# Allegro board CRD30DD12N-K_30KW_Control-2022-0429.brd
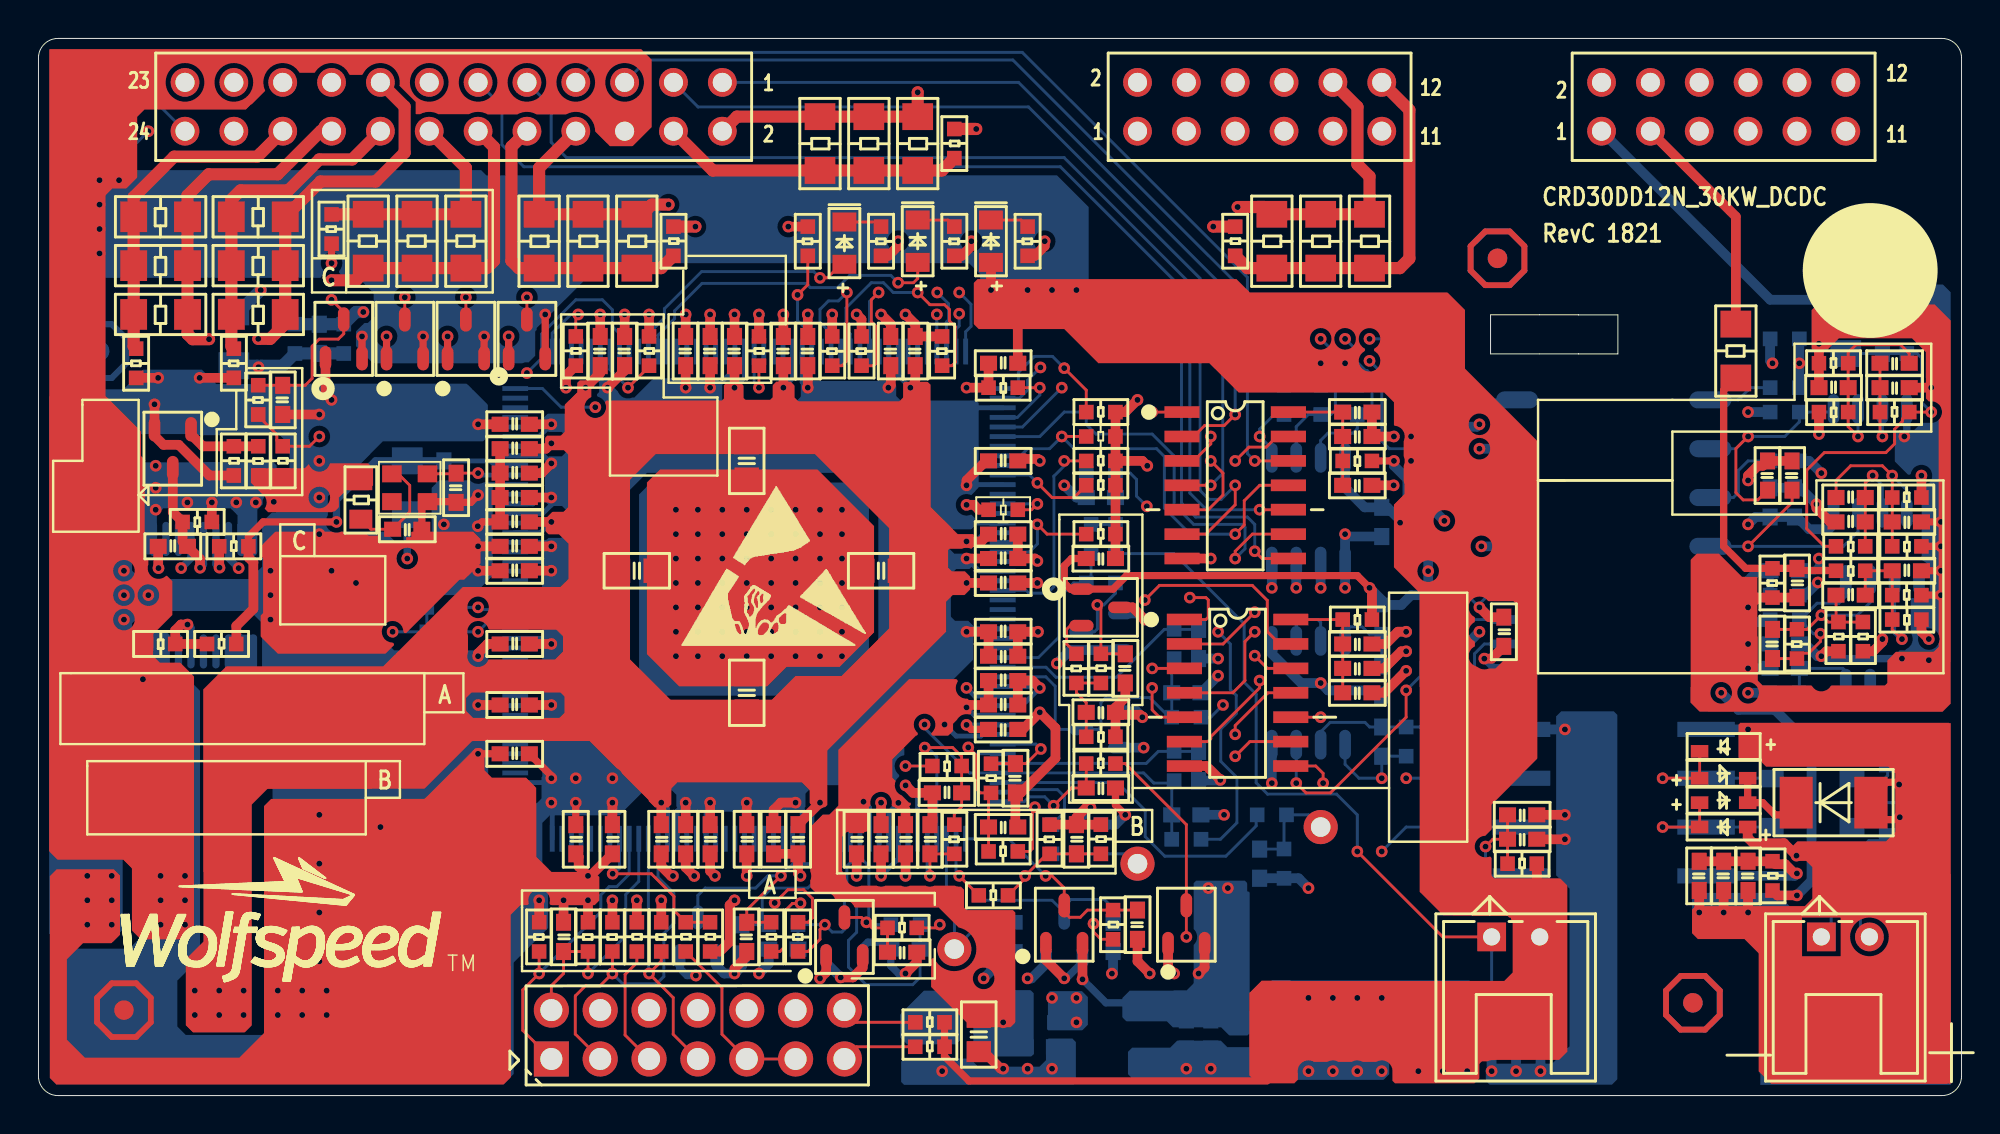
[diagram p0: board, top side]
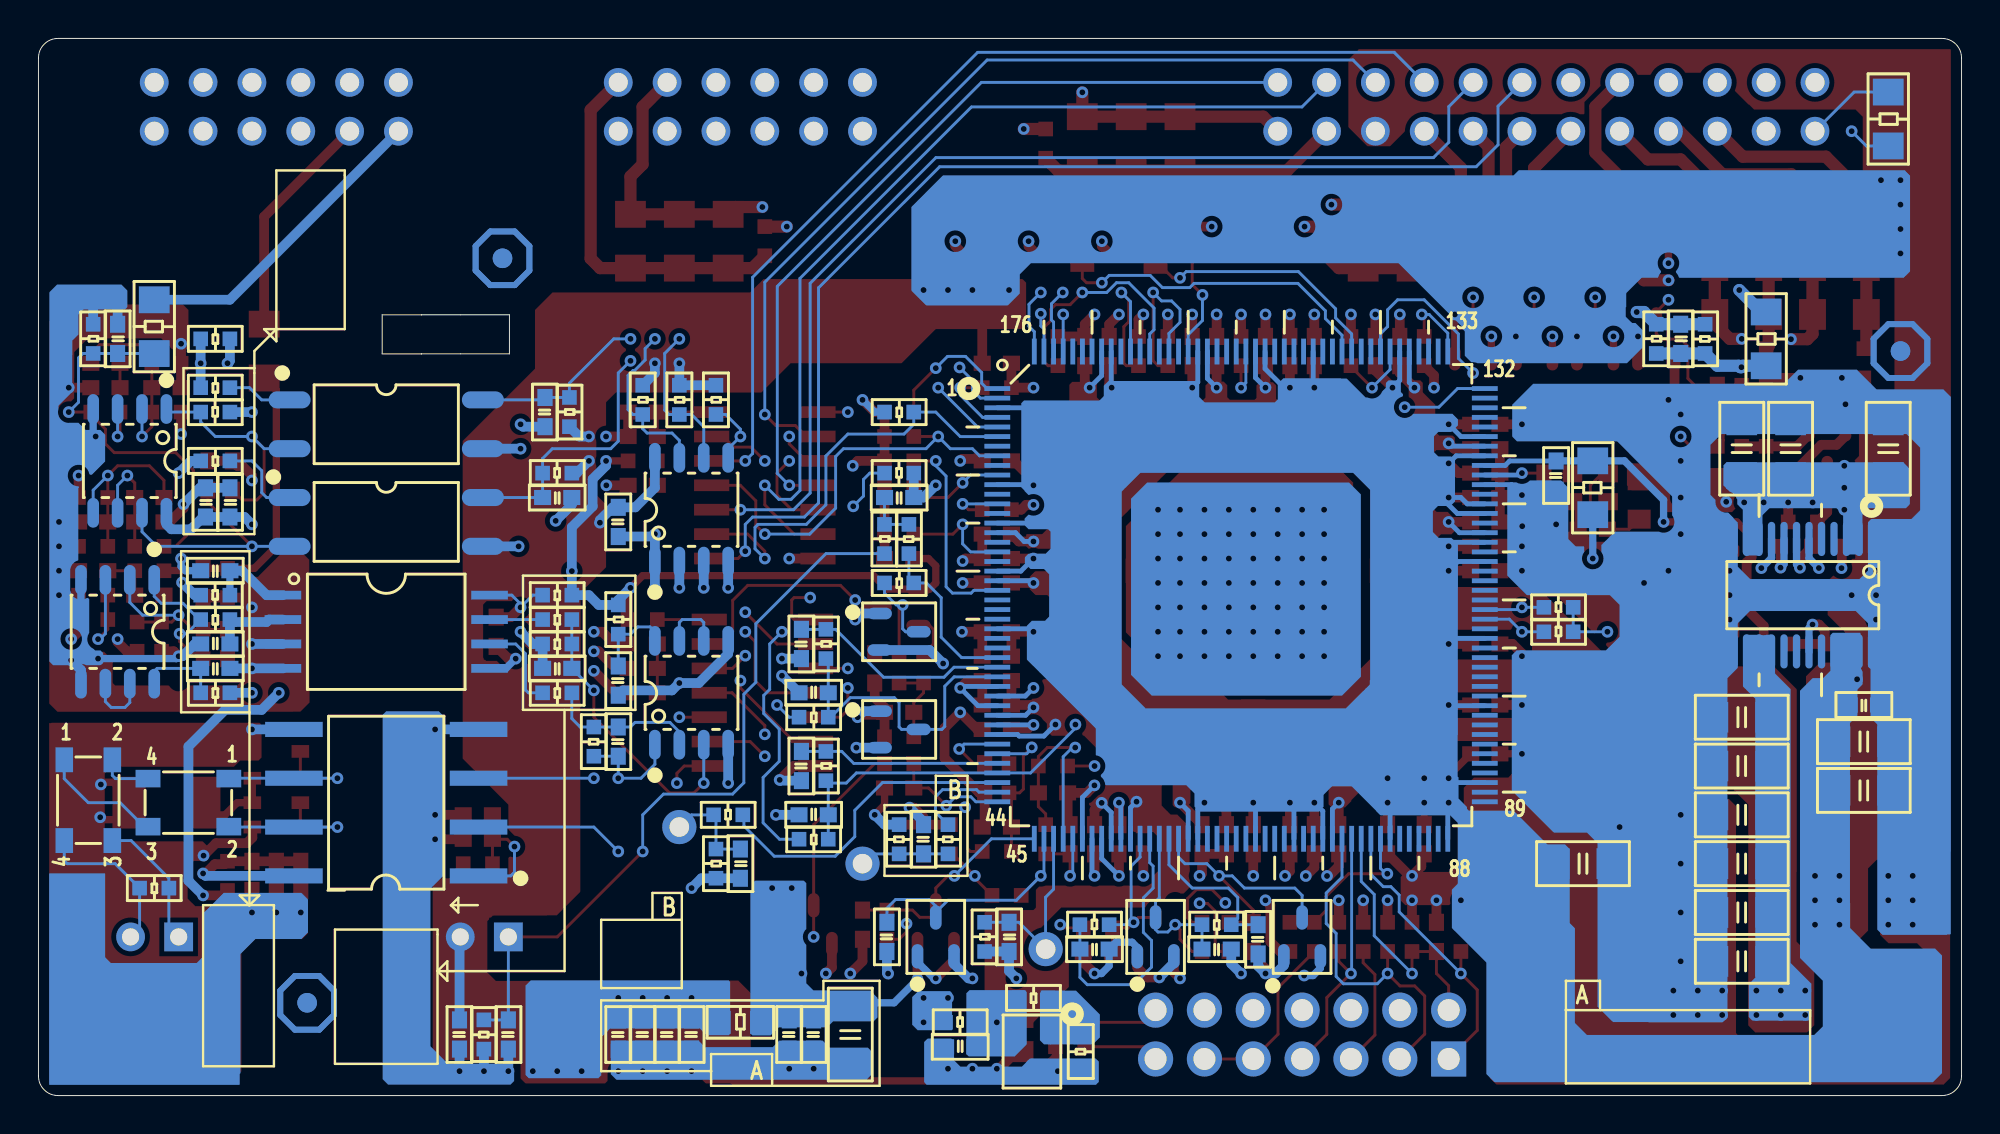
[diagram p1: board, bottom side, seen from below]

Outline 100 x 55 mm; copper layers: TOP, ART02, ART03, BOTTOM. Coordinates in mm from the lower left corner of the outline.
Outline path: 0,53.98 0,1.02 arc(0.3,0.3) 1.02,0 98.98,0 arc(99.7,0.3) 100,1.02 100,53.98 arc(99.7,54.7) 98.98,55 1.02,55 arc(0.3,54.7) 0,53.98 ; 75.51,40.62 80.08,40.62 80.08,40.62 82.13,40.62 82.13,38.59 80.08,38.59 80.08,38.59 75.51,38.59 75.51,40.62

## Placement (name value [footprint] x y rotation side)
C237  22n  [C0603]  91.44 26.67 90 top
C378  0.1u  [C0603]  27.3 8.26 90 top
C396  0.1u  [C0603]  69.85 29.84 270 bottom
C397  680p  [C0603]  52.07 2.54 0 bottom
C398  0.1u  [C0603]  69.85 3.17 270 bottom
C399  0.1u  [C0603]  68.58 3.17 270 bottom
C400  0.1u  [C0603]  67.31 3.17 270 bottom
C401  0.1u  [C0603]  66.04 3.17 270 bottom
C402  0.1u  [C0603]  60.96 3.17 270 bottom
C403  0.1u  [C0603]  59.69 3.17 270 bottom
C404  4.7u  [C1206]  57.78 3.17 270 bottom
C405  1u  [C0603]  78.11 3.17 270 bottom
C407  0.47u  [C0603]  75.56 3.17 270 bottom
C408  0.47u  [C0603]  55.24 31.11 180 bottom
C445  0.1u  [C0603]  90.81 27.3 180 bottom
C446  2.2n  [C0603]  90.81 23.5 0 bottom
C447  0.1u  [C0603]  76.2 24.13 90 top
C448  0.33n  [C0603]  73.03 22.23 180 bottom
C449  0.33n  [C0603]  69.85 18.41 270 bottom
C451  0.47u  [C0603]  69.85 21.59 270 bottom
C452  4.7n  [C0603]  57.15 8.89 270 top
C453  0.15n  [C0603]  97.16 27.3 180 top
C454  0.15n  [C0603]  94.23 26.04 180 top
C455  0.15n  [C0603]  90.17 23.5 270 top
C457  0.47u  [C0603]  90.81 22.23 180 bottom
C458  0.47n  [C0603]  96.52 36.83 0 top
C459  0.1u  [C0603]  93.34 36.83 180 top
C460  0.15n  [C0603]  96.52 38.1 0 top
C462  0.47u  [C0603]  90.04 30.86 90 bottom
C463  2.2n  [C0603]  73.66 35.56 270 bottom
C464  2.2n  [C0603]  73.03 31.11 180 bottom
C465  0.47n  [C0603]  94.23 29.84 180 top
C466  0.15n  [C0603]  94.23 31.11 180 top
C467  0.12n  [C0603]  97.16 29.84 0 top
C471  1u  [C0603]  77.15 14.61 0 top
C472  0.1u  [C0603]  77.15 13.34 0 top
C473  1u  [C0603]  86.36 11.43 270 top
C474  0.1u  [C0603]  88.9 11.43 270 top
C475  0.01u  [C0603]  87.63 11.43 270 top
C488  2.2n  [C0603]  53.98 13.34 90 top
C489  4.7n  [C0603]  55.88 8.26 270 bottom
C492  0.01u  [C0603]  55.24 19.94 0 top
C493  0.01u  [C0603]  56.52 22.23 270 top
C494  0.1u  [C0603]  55.24 27.94 0 top
C496  10u  [C1206]  11.43 33.66 90 bottom
C497  10u  [C1206]  8.89 33.66 90 bottom
C499  0.1u  [C0603]  5.08 20.32 180 bottom
C500  10u  [C1206]  5.08 18.41 180 bottom
C501  10u  [C1206]  5.08 15.88 180 bottom
C504  10u  [C1206]  3.81 33.66 90 bottom
C505  0.1u  [C0603]  6.99 28.57 180 top
C506  10u  [C1206]  19.68 12.06 180 bottom
C507  10u  [C1206]  11.43 14.61 0 bottom
C508  10u  [C1206]  11.43 12.06 0 bottom
C509  10u  [C1206]  11.43 17.14 0 bottom
C510  10u  [C1206]  11.43 9.53 0 bottom
C511  10u  [C1206]  11.43 6.99 0 bottom
C512  2.2u  [C0805]  36.83 33.02 270 top
C513  2.2u  [C0805]  43.81 27.3 180 top
C514  2.2u  [C0805]  36.83 20.95 90 top
C515  2.2u  [C0805]  31.11 27.3 0 top
C516  10u  [C1206]  11.43 19.68 0 bottom
C519  22n  [C0603]  21.08 32.26 270 bottom
C520  0.1u  [C0603]  50.16 38.1 180 top
C521  2.2u  [C0603]  50.16 19.05 0 top
C522  2.2u  [C0603]  45.59 38.73 270 top
C523  2.2u  [C0603]  44.32 38.73 270 top
C524  2.2u  [C0603]  40.01 38.73 270 top
C525  2.2u  [C0603]  38.73 38.73 270 top
C526  2.2u  [C0603]  36.2 38.73 270 top
C527  2.2u  [C0603]  34.92 38.73 270 top
C528  2.2u  [C0603]  33.66 38.73 270 top
C529  2.2u  [C0603]  30.48 38.73 270 top
C530  2.2u  [C0603]  29.21 38.73 270 top
C531  2.2u  [C0603]  24.77 34.92 180 top
C532  2.2u  [C0603]  24.77 33.66 180 top
C533  2.2u  [C0603]  24.77 32.38 180 top
C534  2.2u  [C0603]  24.77 31.11 180 top
C535  2.2u  [C0603]  24.77 29.84 180 top
C536  2.2u  [C0603]  24.77 28.57 180 top
C537  2.2u  [C0603]  24.77 27.3 180 top
C538  2.2u  [C0603]  24.77 23.5 180 top
C539  2.2u  [C0603]  24.77 20.32 180 top
C540  2.2u  [C0603]  24.77 17.78 180 top
C541  2.2u  [C0603]  27.94 13.34 90 top
C542  2.2u  [C0603]  29.84 13.34 90 top
C543  2.2u  [C0603]  32.38 13.34 90 top
C544  2.2u  [C0603]  33.66 13.34 90 top
C545  2.2u  [C0603]  34.92 13.34 90 top
C546  2.2u  [C0603]  36.83 13.34 90 top
C547  2.2u  [C0603]  38.23 13.34 90 top
C548  2.2u  [C0603]  39.5 13.34 90 top
C549  2.2u  [C0603]  45.09 13.34 90 top
C550  2.2u  [C0603]  43.81 13.34 90 top
C551  2.2u  [C0603]  42.55 13.34 90 top
C552  0.1u  [C0603]  50.16 22.86 0 top
C553  0.1u  [C0603]  50.16 33.02 180 top
C554  2.2u  [C0603]  50.16 29.21 180 top
C555  0.1u  [C0603]  50.16 27.94 180 top
C556  2.2u  [C0603]  50.16 26.67 180 top
C557  0.1u  [C0603]  50.16 24.13 180 top
C558  2.2u  [C0603]  50.16 21.59 180 top
C559  2.2u  [C0603]  50.16 20.32 180 top
C560  0.1u  [C0603]  68.58 35.56 0 top
C561  0.01u  [C0603]  68.58 31.75 0 top
C562  1u  [C0603]  68.58 34.29 0 top
C563  0.1u  [C0603]  68.58 23.5 0 top
C564  0.01u  [C0603]  68.58 20.95 0 top
C565  1u  [C0603]  68.58 22.23 0 top
C566  0.47u  [C0603]  91.31 30.86 90 bottom
C592  2.2u  [C0805]  48.9 3.17 270 top
C593  120p  [C0603]  44.91 7.46 0 top
C594  0.47n  [C0603]  95.89 39.37 90 bottom
C595  100n  [C0603]  45.09 7.62 180 bottom
C596  120p  [C0603]  38.73 7.62 180 bottom
C597  100n  [C0603]  36.58 8.13 270 bottom
C598  2.2n  [C0603]  55.24 16 0 top
C687  0.01u  [C0603]  49.53 8.26 90 bottom
C690  0.01u  [C0603]  53.98 13.34 270 bottom
C691  0.01u  [C0603]  63.5 12.06 90 bottom
C697  0.12n  [C0603]  12.7 36.2 270 top
C698  2.2n  [C0603]  14.61 39.37 90 bottom
C699  1n  [C0603]  36.83 8.26 270 top
C703  100n  [C0603]  60.33 23.5 270 bottom
C704  120p  [C0603]  59.69 20.95 0 bottom
C705  100n  [C0603]  60.33 17.14 270 bottom
C706  120p  [C0603]  59.69 14.61 0 bottom
C707  100n  [C0603]  50.8 16.51 270 top
C708  120p  [C0603]  50.16 13.97 0 top
C709  100n  [C0603]  46.35 13.34 90 top
C710  120p  [C0603]  47.24 15.75 180 top
C711  2.2u  [C0603]  19.18 29.46 0 top
C712  0.022n  [C0603]  21.72 31.62 270 top
C713  22n  [C0603]  91.19 32.26 270 top
C714  22n  [C0603]  89.92 32.26 270 top
D85  BAV99  [SOT-23]  55.24 24.13 270 bottom
D86  BAV99  [SOT-23]  34.29 8.26 180 bottom
D89  BAV99  [SOT-23]  53.34 8.89 0 top
D90  BAV99  [SOT-23]  41.91 8.26 180 bottom
D92  BAV99  [SOT-23]  55.24 19.05 270 bottom
D95  BAV99  [SOT-23]  15.88 39.37 0 top
D102  RC-CL-170R-0805  [LED0805]  41.91 44.35 90 top
D103  RC-CL-170R-0805  [LED0805]  45.72 44.45 90 top
D104  RC-CL-170R-0805  [LED0805]  49.53 44.45 90 top
D110  BAS21WS-TP  [SOD-323]  87.63 13.97 180 top
D111  SMBJ15CA  [SMB]  93.34 15.24 180 top
D112  BAS21WS-TP  [SOD-323]  87.63 15.24 0 top
D113  BAS21WS-TP  [SOD-323]  87.63 17.91 180 top
D114  BAS21WS-TP  [SOD-323]  87.63 16.51 0 top
D115  BAV99  [SOT-23]  53.34 8.26 180 bottom
D124  BAV99  [SOT-23]  25.4 39.37 0 top
D125  BAV99  [SOT-23]  22.23 39.37 0 top
D126  BAV99  [SOT-23]  19.05 39.37 0 top
D127  BAV99  [SOT-23]  41.91 8.26 0 top
D128  BAV99  [SOT-23]  59.69 8.89 0 top
DAC_1  TP  [1MMTESTPOINT]  47.62 7.62 180 bottom
DAC_4  TP  [1MMTESTPOINT]  57.15 12.06 0 bottom
DAC_5  TP  [1MMTESTPOINT]  66.67 13.97 180 bottom
J2  PIN2*12-2.54-F  [CON_2MM54_12X2]  21.59 51.44 180 top
J3  PIN2*6-2.54-F  [CON_2MM54_6X2]  63.5 51.44 0 top
J4  PIN2*6-2.54-F  [CON_2MM54_6X2]  87.63 51.44 0 top
J5  2*7P 2.54  [CON_2MM54_7X2]  34.29 3.17 180 top
J11  XHB2.54-2P-F  [CON_2MM54_2X1]  92.71 8.26 180 top
J17  1*2P  [CONNECT_2MM54_2X1]  75.56 8.26 180 top
L21  33uH 0.2A  [R0805]  63.5 3.81 0 bottom
NOREF  -  []  350.41 18.16 0 top
NOREF#2  -  []  0.01 -3.22 0 top
NOREF#3  -  []  30.85 0 90 top
NOREF#4  #VAL  [unnamed#2]  75.87 43.56 0 top
NOREF#5  #VAL  [unnamed#2]  86.03 4.83 0 top
NOREF#6  -  []  38.34 26.64 0 top
NOREF#7  -  []  0.01 -5.17 0 top
NOREF#8  -  []  364.26 48.78 0 top
NOREF#9  -  []  204.89 111.18 0 top
NOREF#10  #VAL  [unnamed#2]  4.45 4.45 0 top
NOREF#11  -  []  95.25 42.93 0 top
NOREF#12  -  []  33.5 0 90 top
NOREF#13  #VAL  [unnamed#2]  75.87 43.56 180 bottom
NOREF#14  #VAL  [unnamed#2]  3.17 38.73 180 bottom
NOREF#15  #VAL  [unnamed#2]  75.87 43.56 180 bottom
NOREF#16  #VAL  [unnamed#2]  86.03 4.83 180 bottom
NOREF#17  #VAL  [unnamed#2]  86.03 4.83 180 bottom
NOREF#18  #VAL  [unnamed#2]  3.17 38.73 180 bottom
Q1  2N7002/SOT  [SOT-23]  6.99 33.66 180 top
R49  620K  [R1206]  3.81 50.81 90 bottom
R58  24K  [R0603]  52.58 13.34 270 top
R133  12K  [R0603]  90.17 26.67 270 top
R327  1R  [R0603]  31.75 38.73 90 top
R400  1R  [R0603]  37.47 38.73 90 top
R404  10k  [R0603]  26.04 8.26 270 top
R405  10k  [R0603]  29.84 8.26 270 top
R406  10k  [R0603]  32.38 8.26 270 top
R407  10k  [R0603]  34.92 8.26 90 top
R408  0  [R0603]  33.66 8.26 90 top
R409  0  [R0603]  31.11 8.26 90 top
R410  470  [R0603]  28.57 8.26 270 top
R411  2.2k  [R0603]  46.35 3.81 180 top
R412  2.2k  [R0603]  46.35 2.54 180 top
R416  2k  [R0603]  55.24 35.56 180 bottom
R417  2k  [R0603]  55.24 34.29 180 top
R418  2k  [R0603]  46.99 38.73 270 top
R419  2k  [R0603]  41.27 38.73 270 top
R420  2k  [R0603]  55.24 29.21 180 top
R421  2k  [R0603]  55.24 35.56 180 top
R422  2k  [R0603]  40.01 44.45 270 top
R423  2k  [R0603]  42.8 38.73 270 top
R424  2k  [R0603]  50.16 36.83 0 top
R425  2k  [R0603]  55.24 33.02 180 top
R437  10k  [R0603]  64.77 36.2 90 bottom
R438  10k  [R0603]  66.67 36.2 90 bottom
R439  10k  [R0603]  68.58 36.2 90 bottom
R440  200  [R0603]  52.07 3.81 0 bottom
R441  1.5k  [R0603]  48.26 5.08 180 bottom
R442  4.7k  [R0603]  45.8 2.29 270 bottom
R443  2k  [R0603]  43.81 44.45 270 top
R444  2k  [R0603]  47.62 44.45 270 top
R445  2k  [R0603]  51.44 44.45 270 top
R446  10k  [R0603]  76.83 3.17 270 bottom
R447  3.3k  [R0603]  56.01 28.96 90 bottom
R482  2k  [R0603]  90.81 24.77 180 bottom
R483  10k  [R0603]  73.03 24.77 180 bottom
R484  10k  [R0603]  73.03 23.5 180 bottom
R485  10k  [R0603]  73.03 20.95 180 bottom
R486  10k  [R0603]  71.12 18.41 270 bottom
R487  2k  [R0603]  55.88 8.89 90 top
R488  150k  [R0603]  94.23 27.3 0 top
R489  100k  [R0603]  97.16 26.04 180 top
R491  100k  [R0603]  91.44 23.5 270 top
R492  1M  [R0603]  97.16 24.77 0 top
R493  1M  [R0603]  94.87 23.88 90 top
R494  150k  [R0603]  93.6 23.88 90 top
R495  2k  [R0603]  96.52 35.56 180 top
R496  2.2k  [R0603]  93.34 35.56 0 top
R497  3.3k  [R0603]  93.34 38.1 180 top
R500  3K  [R0603]  90.81 36.83 180 bottom
R502  15k  [R0603]  72.39 35.56 90 bottom
R503  3K  [R0603]  90.81 33.02 180 bottom
R505  15k  [R0603]  73.03 32.38 0 bottom
R506  1k  [R0603]  94.23 28.57 0 top
R507  15k  [R0603]  97.16 31.11 180 top
R508  1k  [R0603]  97.16 28.57 0 top
R514  620  [R0603]  20.95 24.13 0 bottom
R515  10k  [R0603]  20.95 25.4 0 bottom
R516  0  [R0603]  90.17 11.43 90 top
R517  120  [R0603]  93.98 10.79 180 bottom
R528  24k  [R0603]  55.24 13.34 90 top
R529  1k  [R0603]  49.66 10.41 180 top
R532  100  [R0603]  53.98 22.23 270 top
R533  470k  [R0603]  55.24 18.67 0 top
R534  3.3k  [R0603]  55.24 22.23 90 top
R536  10k  [R0603]  8.26 29.84 0 top
R537  1.5k  [R0603]  11.43 33.02 270 top
R538  12k  [R0603]  10.16 33.02 90 top
R540  100k  [R0603]  6.35 23.5 0 top
R541  0R  [R0603]  9.53 23.5 180 top
R546  10k  [R1206]  19.18 31.62 270 bottom
R547  0  [R0603]  10.16 28.57 180 top
R549  2.2R  [R0603]  68.58 33.02 0 top
R550  2.2R  [R0603]  68.58 24.77 0 top
R569  10k  [R0603]  90.81 35.56 0 bottom
R573  620k  [R1206]  88.27 38.73 270 top
R574  560k  [R1206]  93.98 40.01 270 bottom
R575  12K  [R0603]  97.16 39.37 90 bottom
R580  20R  [R1206]  11.43 45.72 0 top
R581  20R  [R1206]  11.43 43.18 0 top
R582  20R  [R1206]  11.43 40.64 0 top
R583  100  [R0603]  44.91 8.73 180 top
R588  0  [R0603]  10.16 38.1 270 top
R592  10R  [R0603]  90.81 20.95 180 bottom
R593  10R  [R0603]  90.81 26.04 0 bottom
R594  10R  [R0603]  73.03 26.04 180 bottom
R595  10R  [R0603]  69.85 24.77 90 bottom
R597  10R  [R0603]  90.81 39.37 180 bottom
R598  10R  [R0603]  77.15 12.06 180 top
R599  1k  [R0603]  45.09 8.89 0 bottom
R602  100  [R0603]  39.5 8.26 270 top
R603  20R  [R1206]  6.35 45.72 0 top
R604  20R  [R1206]  6.35 43.18 0 top
R605  20R  [R1206]  6.35 40.64 0 top
R606  1k  [R0603]  38.73 8.89 180 bottom
R607  1k  [R0603]  55.24 17.27 180 top
R610  2k  [R0603]  55.24 31.75 180 top
R611  2k  [R0603]  50.16 30.48 0 top
R673  100k  [R0603]  50.8 8.26 90 bottom
R678  1k  [R0603]  52.7 13.34 270 bottom
R679  1k  [R0603]  64.14 14.61 0 bottom
R680  100k  [R0603]  55.24 13.34 270 bottom
R681  100k  [R0603]  64.77 12.06 90 bottom
R689  1k  [R0603]  11.43 36.2 270 top
R691  10k  [R0603]  12.7 33.02 90 top
R692  24k  [R0603]  15.88 39.37 90 bottom
R693  1k  [R0603]  38.1 8.26 90 top
R694  620K  [R1206]  10.16 39.37 90 bottom
R695  24K  [R0603]  13.34 39.37 270 bottom
R702  0  [R0603]  5.08 38.1 270 top
R703  2k  [R0603]  27.94 38.73 90 top
R704  2k  [R0603]  55.24 32.38 0 bottom
R705  0  [R0603]  15.24 45.09 270 top
R706  1k  [R0603]  59.05 23.5 90 bottom
R707  100  [R0603]  59.69 19.68 180 bottom
R708  20R  [R1206]  22.23 44.45 270 top
R709  20R  [R1206]  19.68 44.45 270 top
R710  20R  [R1206]  17.14 44.45 270 top
R711  0  [R0603]  47.62 49.53 90 top
R712  1k  [R0603]  59.05 17.14 90 bottom
R713  100  [R0603]  59.69 13.34 180 bottom
R714  20R  [R1206]  40.64 49.53 90 top
R715  20R  [R1206]  45.72 49.53 90 top
R716  20R  [R1206]  43.18 49.53 90 top
R717  0  [R0603]  33.02 44.45 90 top
R718  1k  [R0603]  49.53 16.51 90 top
R719  100  [R0603]  50.16 12.7 180 top
R720  20R  [R1206]  31.11 44.45 90 top
R721  20R  [R1206]  28.57 44.45 90 top
R722  20R  [R1206]  26.04 44.45 90 top
R723  0  [R0603]  62.23 44.45 90 top
R724  1k  [R0603]  47.62 13.34 270 top
R725  100  [R0603]  47.24 17.14 0 top
R726  20R  [R1206]  69.22 44.45 90 top
R727  20R  [R1206]  66.67 44.45 90 top
R728  20R  [R1206]  64.14 44.45 90 top
R729  NA  [R0603]  54.74 28.96 270 bottom
R730  0  [R0603]  55.24 26.67 180 bottom
R731  10R  [R0805]  16.76 30.99 90 top
T1  TRNSFMR TV105  [4532]  92.2 15.24 0 bottom
T2  TRNSFMR TV105  [4532]  97.41 15.37 270 bottom
U9  AZ431  [SOT23_1-32]  48.34 2.29 0 bottom
U28  TMS320F28377D  [LQFP176-050-2424]  37.47 26.04 270 bottom
U32  24C16BT-I/SN  [SOIC-8]  66.04 30.48 90 bottom
U43  ACPL-C870-500E  [SSO-8]  81.92 24.13 270 bottom
U44  OPA2376  [SOIC-8]  95.89 24.13 270 bottom
U45  OPA2376  [SOIC-8]  66.04 20.95 90 bottom
U48  LM2903  [SOIC-8]  95.25 33.02 270 bottom
U53  1050  [SO-G8]  81.92 15.24 0 bottom
U55  LM50CIM3  [SOT-23]  55.24 25.4 270 top
U57  TPS70445PWP_TSSOP24  [TSSOP24]  8.26 26.04 270 bottom
U58  MC74VHCT50A_SOIC14  [SOIC14]  62.23 31.75 0 top
U59  MC74VHCT50A_SOIC14  [SOIC14]  62.35 20.95 0 top
U60  -  [TCLT1003]  81.92 34.92 180 bottom
U61  -  [TCLT1003]  81.92 29.84 180 bottom
Y3  OSC4_250x200  [OSC4_250X200]  19.3 31.62 0 top

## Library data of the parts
C237 C378 C396-C403 C405 C407 C408 C445-C449 C451-C455 C457-C460 C462-C467 C471-C475 C488 C489 C492-C494 C499 C505 C519-C566 C593-C598 C687 C690 C691 C697-C699 C703-C710 = C0603: Tolerance: #TOL; User Part Number: HAMP
C404 C496 C497 C500 C501 C504 C506-C511 C516 = C1206: Tolerance: #TOL; User Part Number: HAMP
C512-C515 C592 = C0805: Tolerance: #TOL; User Part Number: HAMP
C711-C714 = C0603: User Part Number: HAMP; Tolerance: #TOL
D85 D86 D89 D90 D92 D95 D115 D124-D128 Q1 U55 = SOT-23: Tolerance: #TOL; User Part Number: HAMP
D102-D104 = LED0805: Tolerance: #TOL; User Part Number: HAMP
D110 D112-D114 = SOD-323: Tolerance: #TOL; User Part Number: HAMP
D111 = SMB: Tolerance: #TOL; User Part Number: HAMP
DAC_1 DAC_4 DAC_5 = 1MMTESTPOINT: User Part Number: HAMP; Tolerance: #TOL
J2 = CON_2MM54_12X2: Tolerance: #TOL; User Part Number: HAMP
J3 J4 = CON_2MM54_6X2: Tolerance: #TOL; User Part Number: HAMP
J5 = CON_2MM54_7X2: Tolerance: #TOL; User Part Number: HAMP
J11 = CON_2MM54_2X1: Tolerance: #TOL; User Part Number: HAMP
J17 = CONNECT_2MM54_2X1: Tolerance: #TOL; User Part Number: HAMP
L21 = R0805: Tolerance: #TOL; User Part Number: HAMP
NOREF#4 NOREF#5 NOREF#10 NOREF#13-NOREF#18 = -: Tolerance: #TOL; User Part Number: HAMP
R49 R546 R573 R574 R580-R582 R603-R605 R694 R708-R710 R714-R716 R720-R722 R726-R728 = R1206: Tolerance: #TOL; User Part Number: HAMP
R58 R133 R327 R400 R404-R412 R416-R425 R437-R447 R482-R489 R491-R497 R500 R502 R503 R505-R508 R514-R517 R528 R529 R532-R534 R536-R538 R540 R541 R547 R549 R550 R569 R575 R583 R588 R592-R595 R597-R599 R602 R606 R607 R610 R611 R673 R678-R681 R689 R691-R693 R695 R702-R707 R711-R713 R717-R719 R723-R725 R729 R730 = R0603: Tolerance: #TOL; User Part Number: HAMP
R731 = R0805: User Part Number: HAMP; Tolerance: #TOL
T1 T2 = 4532: Tolerance: #TOL; User Part Number: HAMP
U9 = SOT23_1-32: Tolerance: #TOL; User Part Number: HAMP
U28 = LQFP176-050-2424: Tolerance: #TOL; User Part Number: HAMP
U32 U44 U45 U48 = SOIC-8: Tolerance: #TOL; User Part Number: HAMP
U43 = SSO-8: Tolerance: #TOL; User Part Number: HAMP
U53 = SO-G8: Tolerance: #TOL; User Part Number: HAMP
U57 = TSSOP24: Tolerance: #TOL; User Part Number: HAMP
U58 U59 = SOIC14: Tolerance: #TOL; User Part Number: HAMP
U60 U61 = TCLT1003: Tolerance: #TOL; User Part Number: HAMP
Y3 = OSC4_250X200: Tolerance: #TOL; User Part Number: HAMP

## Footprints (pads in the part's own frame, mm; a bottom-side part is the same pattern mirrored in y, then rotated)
1MMTESTPOINT
  round 1.778 hole 1.016: 1(0,0)
4532
  rect 1.295x0.914 smd: 1(-2.1,-1.25) 2(-2.1,1.25) 3(2.1,1.25) 4(2.1,-1.25)
C0603
  rect 0.889x0.787 smd: 1(-0.76,0) 2(0.76,0)
C0805
  rect 1.092x1.27 smd: 1(-0.89,0) 2(0.89,0)
C1206
  rect 1.397x1.6 smd: 1(-1.4,0) 2(1.4,0)
CON_2MM54_2X1
  rect 1.499x1.499 hole 0.889: 1(0,0)
  round 1.499 hole 0.889: 2(-2.5,0)
CON_2MM54_6X2
  round 1.499 hole 0.991: 1(-6.35,-1.27) 2(-6.35,1.27) 3(-3.81,-1.27) 4(-3.81,1.27) 5(-1.27,-1.27) 6(-1.27,1.27) 7(1.27,-1.27) 8(1.27,1.27) 9(3.81,-1.27) 10(3.81,1.27) 11(6.35,-1.27) 12(6.35,1.27)
CON_2MM54_7X2
  rect 1.829x1.829 hole 1.143: 1(7.62,1.271)
  round 1.829 hole 1.143: 2(7.62,-1.271) 3(5.08,1.271) 4(5.08,-1.271) 5(2.54,1.271) 6(2.54,-1.271) 7(0,1.271) 8(0,-1.271) 9(-2.54,1.271) 10(-2.54,-1.271) 11(-5.08,1.271) 12(-5.08,-1.271) 13(-7.62,1.271) 14(-7.62,-1.271)
CON_2MM54_12X2
  round 1.499 hole 0.991: 1(-13.97,-1.27) 2(-13.97,1.27) 3(-11.43,-1.27) 4(-11.43,1.27) 5(-8.89,-1.27) 6(-8.89,1.27) 7(-6.35,-1.27) 8(-6.35,1.27) 9(-3.81,-1.27) 10(-3.81,1.27) 11(-1.27,-1.27) 12(-1.27,1.27) 13(1.27,-1.27) 14(1.27,1.27) 15(3.81,-1.27) 16(3.81,1.27) 17(6.35,-1.27) 18(6.35,1.27) 19(8.89,-1.27) 20(8.89,1.27) 21(11.43,-1.27) 22(11.43,1.27) 23(13.97,-1.27) 24(13.97,1.27)
CONNECT_2MM54_2X1
  rect 1.499x1.499 hole 0.889: 1(0,0)
  round 1.499 hole 0.889: 2(-2.5,0)
LED0805
  rect 0.991x1.245 smd: 1(1.1,0) 2(-1.1,0)
LQFP176-050-2424
  rect 8.636x8.636 smd: 0(0,0)
  rect 0.254x1.346 smd: 1(-10.75,-12.675) 2(-10.25,-12.675) 3(-9.75,-12.675) 4(-9.25,-12.675) 5(-8.75,-12.675) 6(-8.25,-12.675) 7(-7.75,-12.675) 8(-7.25,-12.675) 9(-6.75,-12.675) 10(-6.25,-12.675) 11(-5.75,-12.675) 12(-5.25,-12.675) 13(-4.75,-12.675) 14(-4.25,-12.675) 15(-3.75,-12.675) 16(-3.25,-12.675) 17(-2.75,-12.675) 18(-2.25,-12.675) 19(-1.75,-12.675) 20(-1.25,-12.675) 21(-0.75,-12.675) 22(-0.25,-12.675) 23(0.25,-12.675) 24(0.75,-12.675) 25(1.25,-12.675) 26(1.75,-12.675) 27(2.25,-12.675) 28(2.75,-12.675) 29(3.25,-12.675) 30(3.75,-12.675) 31(4.25,-12.675) 32(4.75,-12.675) 33(5.25,-12.675) 34(5.75,-12.675) 35(6.25,-12.675) 36(6.75,-12.675) 37(7.25,-12.675) 38(7.75,-12.675) 39(8.25,-12.675) 40(8.75,-12.675) 41(9.25,-12.675) 42(9.75,-12.675) 43(10.25,-12.675) 44(10.75,-12.675) 89(10.75,12.675) 90(10.25,12.675) 91(9.75,12.675) 92(9.25,12.675) 93(8.75,12.675) 94(8.25,12.675) 95(7.75,12.675) 96(7.25,12.675) 97(6.75,12.675) 98(6.25,12.675) 99(5.75,12.675) 100(5.25,12.675) 101(4.75,12.675) 102(4.25,12.675) 103(3.75,12.675) 104(3.25,12.675) 105(2.75,12.675) 106(2.25,12.675) 107(1.75,12.675) 108(1.25,12.675) 109(0.75,12.675) 110(0.25,12.675) 111(-0.25,12.675) 112(-0.75,12.675) 113(-1.25,12.675) 114(-1.75,12.675) 115(-2.25,12.675) 116(-2.75,12.675) 117(-3.25,12.675) 118(-3.75,12.675) 119(-4.25,12.675) 120(-4.75,12.675) 121(-5.25,12.675) 122(-5.75,12.675) 123(-6.25,12.675) 124(-6.75,12.675) 125(-7.25,12.675) 126(-7.75,12.675) 127(-8.25,12.675) 128(-8.75,12.675) 129(-9.25,12.675) 130(-9.75,12.675) 131(-10.25,12.675) 132(-10.75,12.675)
  rect 1.346x0.254 smd: 45(12.675,-10.75) 46(12.675,-10.25) 47(12.675,-9.75) 48(12.675,-9.25) 49(12.675,-8.75) 50(12.675,-8.25) 51(12.675,-7.75) 52(12.675,-7.25) 53(12.675,-6.75) 54(12.675,-6.25) 55(12.675,-5.75) 56(12.675,-5.25) 57(12.675,-4.75) 58(12.675,-4.25) 59(12.675,-3.75) 60(12.675,-3.25) 61(12.675,-2.75) 62(12.675,-2.25) 63(12.675,-1.75) 64(12.675,-1.25) 65(12.675,-0.75) 66(12.675,-0.25) 67(12.675,0.25) 68(12.675,0.75) 69(12.675,1.25) 70(12.675,1.75) 71(12.675,2.25) 72(12.675,2.75) 73(12.675,3.25) 74(12.675,3.75) 75(12.675,4.25) 76(12.675,4.75) 77(12.675,5.25) 78(12.675,5.75) 79(12.675,6.25) 80(12.675,6.75) 81(12.675,7.25) 82(12.675,7.75) 83(12.675,8.25) 84(12.675,8.75) 85(12.675,9.25) 86(12.675,9.75) 87(12.675,10.25) 88(12.675,10.75) 133(-12.675,10.75) 134(-12.675,10.25) 135(-12.675,9.75) 136(-12.675,9.25) 137(-12.675,8.75) 138(-12.675,8.25) 139(-12.675,7.75) 140(-12.675,7.25) 141(-12.675,6.75) 142(-12.675,6.25) 143(-12.675,5.75) 144(-12.675,5.25) 145(-12.675,4.75) 146(-12.675,4.25) 147(-12.675,3.75) 148(-12.675,3.25) 149(-12.675,2.75) 150(-12.675,2.25) 151(-12.675,1.75) 152(-12.675,1.25) 153(-12.675,0.75) 154(-12.675,0.25) 155(-12.675,-0.25) 156(-12.675,-0.75) 157(-12.675,-1.25) 158(-12.675,-1.75) 159(-12.675,-2.25) 160(-12.675,-2.75) 161(-12.675,-3.25) 162(-12.675,-3.75) 163(-12.675,-4.25) 164(-12.675,-4.75) 165(-12.675,-5.25) 166(-12.675,-5.75) 167(-12.675,-6.25) 168(-12.675,-6.75) 169(-12.675,-7.25) 170(-12.675,-7.75) 171(-12.675,-8.25) 172(-12.675,-8.75) 173(-12.675,-9.25) 174(-12.675,-9.75) 175(-12.675,-10.25) 176(-12.675,-10.75)
OSC4_250X200
  rect 1.016x0.889 smd: 1(-0.925,-0.725) 2(0.925,-0.725) 3(0.925,0.725) 4(-0.925,0.725)
R0603
  rect 0.762x0.762 smd: 1(-0.76,0) 2(0.76,0)
R0805
  rect 0.991x1.194 smd: 1(-1,0) 2(1,0)
R1206
  rect 1.397x1.6 smd: 1(-1.4,0) 2(1.4,0)
SMB
  rect 1.727x2.692 smd: 1(-1.943,0) 2(1.943,0)
SO-G8
  rect 2.997x0.787 smd: 1(-4.8,3.81) 2(-4.8,1.27) 3(-4.8,-1.27) 4(-4.8,-3.81) 5(4.8,-3.81) 6(4.8,-1.27) 7(4.8,1.27) 8(4.8,3.81)
SOD-323
  rect 0.914x0.66 smd: 1(-1.25,0) 2(1.25,0)
SOIC14
  rect 1.829x0.61 smd: 1(-2.765,3.81) 2(-2.765,2.54) 3(-2.765,1.27) 4(-2.765,0) 5(-2.765,-1.27) 6(-2.765,-2.54) 7(-2.765,-3.81) 8(2.765,-3.81) 9(2.765,-2.54) 10(2.765,-1.27) 11(2.765,0) 12(2.765,1.27) 13(2.765,2.54) 14(2.765,3.81)
SOIC-8
  oval 1.549x0.61 smd: 1(-2.7,1.905) 2(-2.7,0.635) 3(-2.7,-0.635) 4(-2.7,-1.905) 5(2.7,-1.905) 6(2.7,-0.635) 7(2.7,0.635) 8(2.7,1.905)
SOT23_1-32
  oval 0.61x1.27 smd: 1(-0.95,-1.01) 2(0.95,-1.01) 3(0,1.01)
SOT-23
  oval 0.61x1.27 smd: 1(-0.95,-1.01) 2(0.95,-1.01) 3(0,1.01)
SSO-8
  rect 0.457x1.905 smd: 1(-1.905,-5.373) 2(-0.635,-5.373) 3(0.635,-5.373) 4(1.905,-5.373) 5(1.905,5.373) 6(0.635,5.373) 7(-0.635,5.373) 8(-1.905,5.373)
TCLT1003
  oval 2.184x0.889 smd: 1(-5.025,1.27) 2(-5.025,-1.27) 3(5.025,-1.27) 4(5.025,1.27)
TSSOP24
  oval 1.778x0.381 smd: 1(-2.925,3.575) 2(-2.925,2.925) 3(-2.925,2.275) 4(-2.925,1.625) 5(-2.925,0.975) 6(-2.925,0.325) 7(-2.925,-0.325) 8(-2.925,-0.975) 9(-2.925,-1.625) 10(-2.925,-2.275) 11(-2.925,-2.925) 12(-2.925,-3.575) 13(2.925,-3.575) 14(2.925,-2.925) 15(2.925,-2.275) 16(2.925,-1.625) 17(2.925,-0.975) 18(2.925,-0.325) 19(2.925,0.325) 20(2.925,0.975) 21(2.925,1.625) 22(2.925,2.275) 23(2.925,2.925) 24(2.925,3.575)
  rect 1.651x3.937 smd: 25(0,0)
unnamed#2
  round 1.016 smd: 1(0,0)

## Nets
AGND: C378.2 C396.2 C397.2 C398.2 C399.2 C400.2 C401.2 C402.2 C403.2 C404.2 C405.2 C407.2 C408.2 C447.1 C448.1 C451.2 C452.2 C463.2 C464.2 C471.2 C472.2 C488.2 C489.2 C492.2 C493.2 C494.2 C496.2 C497.2 C499.2 C500.2 C501.2 C504.2 C505.2 C506.2 C507.2 C508.2 C509.2 C510.2 C511.2 C512.2 C513.2 C514.2 C515.2 C516.2 C519.2 C520.2 C521.2 C522.1 C523.1 C524.1 C525.1 C526.1 C527.1 C528.1 C529.1 C530.1 C531.2 C532.2 C533.2 C534.2 C535.2 C536.2 C537.2 C538.2 C539.2 C540.2 C541.1 C542.1 C543.1 C544.1 C545.1 C546.1 C547.1 C548.1 C549.1 C550.1 C551.1 C552.2 C553.1 C554.1 C555.1 C556.1 C557.1 C558.1 C559.1 C560.2 C561.2 C562.2 C563.2 C564.2 C565.2 C592.2 C593.2 C595.2 C596.2 C597.2 C598.2 C687.1 C690.1 C691.1 C697.2 C698.2 C699.2 C703.2 C704.2 C705.2 C706.2 C707.2 C708.2 C709.2 C710.2 C711.2 C712.2 D85.1 D86.1 D89.1 D90.1 D92.1 D95.1 D115.1 D124.1 D125.1 D126.1 D127.1 D128.1 J2.13 J2.17 J2.19 J2.21 J3.6 J3.8 J5.4 J5.6 J5.8 J5.10 J5.12 Q1.2 R58.1 R410.1 R416.1 R417.1 R418.1 R419.1 R420.1 R421.1 R422.1 R423.1 R424.1 R425.1 R442.2 R443.2 R444.2 R445.2 R446.2 R484.1 R528.2 R533.2 R538.1 R588.2 R610.1 R611.1 R673.1 R680.1 R681.1 R692.2 R695.1 R702.2 R703.1 R704.1 R705.2 R711.2 R717.2 R723.2 U9.3 U28.0 U28.32 U28.33 U28.34 U28.50 U28.51 U28.52 U28.122 U32.1 U32.2 U32.3 U32.4 U43.5 U45.4 U45.5 U53.4 U55.3 U57.1 U57.6 U57.9 U57.12 U57.13 U57.24 U57.25 U58.7 U59.7 U60.3 U61.3 Y3.2
SGND: C237.1 C445.1 C446.2 C453.1 C457.2 C458.2 C459.2 C462.2 C465.2 C467.2 C566.2 C594.2 C713.1 C714.1 J4.2 R133.2 R489.1 R494.1 R497.2 R508.2 R575.2 U43.3 U43.4 U44.4 U44.5 U48.4
VDD: C507.1 C508.1 C509.1 C510.1 C511.1 C512.1 C513.1 C514.1 C515.1 C516.1 C522.2 C525.2 C526.2 C530.2 C532.1 C535.1 C543.2 C548.2 C554.2 C556.2 U28.16 U28.21 U28.61 U28.76 U28.117 U28.126 U28.137 U28.153 U28.158 U28.169 U57.14 U57.15 U57.16
/TRST_P: C378.1 J5.2 R410.2 U28.79
/WP_PFC: R439.1 U28.175 U32.7
_AD_DCINPUT: C489.1 D115.3 R529.2 U28.46
_AD_DCINPUT_OV: C699.1 D86.3 R693.2 U28.60
_AD_DCTEMP: C408.1 R447.2 R729.1
_OUTPUT_OC: C697.1 D95.3 R689.1 U28.2
A_ADC: C596.1 D90.3 R602.2 R606.1 U28.58
A_ADC1: C597.1 R606.2 U28.59
AD_AIR_TEMP: C493.1 D85.3 R534.2 R730.1
AD_DCVOLT1: C452.1 D89.3 R487.2 U28.45
B_ADC: C593.1 D127.3 R583.2 R599.1 U28.56
C_ADC: C704.1 D92.3 R706.1 R707.2 U28.31
CAN5V_GND: C473.2 C474.2 C475.2 D110.1 D111.1 D113.1 J4.11 U53.5
CAN_5V: J4.12 R516.1
CANRX: R514.2 U28.108 U53.2
CANTX: R515.2 U28.109 U28.140 U53.3
CS_A: J2.18 R602.1 R603.2 R604.2 R605.2
CS_B: J2.15 R580.2 R581.2 R582.2 R583.1
CS_C: J2.12 R707.1 R708.2 R709.2 R710.2
CS_RTN_A: J2.20 R603.1 R604.1 R605.1 R702.1
CS_RTN_B: J2.16 R580.1 R581.1 R582.1 R588.1
CS_RTN_C: J2.14 R705.1 R708.1 R709.1 R710.1
DC-OV: J2.22 R694.2
DC_FB: J2.24 R49.2
DCOVP: C463.1 R502.2 U28.176 U60.4
DCPWM1A_1H: J2.3 U58.6
DCPWM1A_1HH: R419.2 U28.162 U58.5
DCPWM1A_1L: J2.1 U58.4
DCPWM1A_1LL: R418.2 U28.164 U58.3
DCPWM2A_2H: J2.7 U58.12
DCPWM2A_2HH: R420.2 U28.18 U58.13
DCPWM2A_2L: J2.5 U58.2
DCPWM2A_2LL: R421.2 U28.1 U58.1
DCPWM3A_3H: J2.11 U58.8
DCPWM3A_3HH: R416.2 U58.9
DCPWM3A_3L: J2.9 U58.10
DCPWM3A_3LL: R417.2 U28.8 U58.11
DCSHORT: C464.1 R505.2 U28.5 U61.4
DCVOLT1: C455.2 R482.1 R491.2 U44.1
IOUT_ADC: D128.3 J3.4 R607.1
OUTPUT_OC: J3.2 R689.2 R691.2
P_ADREF3.2V: C397.1 C549.2 C551.2 C558.2 C559.2 C592.1 R440.1 R441.1 U9.2 U28.35 U28.37 U28.53 U28.55
P_SCL: R438.1 U28.174 U32.6
P_SDA: R437.1 U28.173 U32.5
P_WD_GREEN: D102.2 U28.143
P_WD_RED: D103.2 U28.144
PCS_ADC1: C703.1 R706.2 U28.30
RLYCTRL11: R703.2 U28.133
RLYCTRL22: R704.2 U28.132
SA_ADC: C706.1 D124.3 R712.1 R713.2 U28.41
SA_ADC1: C705.1 R712.2 U28.40
SB_ADC: C708.1 D125.3 R718.1 R719.2 U28.39
SB_ADC1: C707.1 R718.2 U28.38
SC_ADC: C710.1 D126.3 R724.1 R725.2 U28.48
SC_ADC1: C709.1 R724.2 U28.49
SCS_A: J2.2 R713.1 R714.2 R715.2 R716.2
SCS_B: J2.8 R719.1 R720.2 R721.2 R722.2
SCS_C: J3.10 R725.1 R726.2 R727.2 R728.2
SCS_RTN_A: J2.4 R711.1 R714.1 R715.1 R716.1
SCS_RTN_B: J2.10 R717.1 R720.1 R721.1 R722.1
SCS_RTN_C: J3.12 R723.1 R726.1 R727.1 R728.1
SR-PWM-A: J3.1 U59.12
SR-PWM-AA: R422.2 U28.160 U59.13
SR-PWM-B: J3.3 U59.2
SR-PWM-BB: R423.2 U28.166 U59.1
SR-PWM-C: J3.5 U59.4
SR-PWM-CC: R424.2 U28.4 U59.3
SR-PWM-D: J3.7 U59.6
SR-PWM-DD: R425.2 U28.22 U59.5
SR-PWM-E: J3.9 U59.8
SR-PWM-EE: R610.2 U28.10 U59.9
SR-PWM-F: J3.11 U59.10
SR-PWM-FF: R611.2 U28.13 U59.11
TCK_P: R407.2 R408.2 U28.81
TDI_P: J5.3 R405.2 U28.77
TDO_P: J5.7 R406.2 U28.78
TMS_P: J5.1 R404.2 U28.80
VO1+: J4.1 R574.1
VO2+: J4.3 R573.1
VP3.3A: C402.1 C403.1 C404.1 C521.1 C550.2 D85.2 D86.2 D89.2 D90.2 D92.2 D115.2 D127.2 D128.2 L21.1 U28.36 U28.54
VP3.3D: C396.1 C398.1 C399.1 C400.1 C401.1 C405.1 C499.1 C500.1 C501.1 C506.1 C520.1 C523.2 C524.2 C527.2 C528.2 C529.2 C531.1 C533.1 C534.1 C536.1 C537.1 C538.1 C539.1 C540.1 C541.2 C542.2 C544.2 C545.2 C546.2 C547.2 C552.1 C553.2 C555.2 C557.2 D95.2 D104.2 D124.2 D125.2 D126.2 J2.6 J17.2 L21.2 R327.2 R400.2 R404.1 R405.1 R406.1 R407.1 R409.2 R411.1 R412.1 R437.2 R438.2 R439.2 R502.1 R505.1 R537.2 R540.1 R546.2 R598.1 R691.1 R731.2 U28.3 U28.11 U28.15 U28.20 U28.26 U28.62 U28.68 U28.72 U28.75 U28.82 U28.88 U28.91 U28.99 U28.106 U28.114 U28.116 U28.119 U28.120 U28.125 U28.127 U28.138 U28.147 U28.152 U28.159 U28.168 U32.8 U57.21 U57.22 U57.23
VP+5V: C494.1 C496.1 C497.1 C504.1 J2.23 R440.2 R536.2 R549.2 R550.2 R594.2 R595.2 U55.1 U57.2 U57.3 U57.10 U57.11
VS+5V: J4.4 R492.2 R493.1 R496.1 R500.1 R503.1 R507.1 R569.1 R592.2 R593.2 R597.1
XCLK: C712.1 U28.123 Y3.3
XRS: C519.1 R541.1 R546.1 R547.1 U28.124
N16779815: R327.1 U28.139
N16830570: R441.2 R442.1 U9.1
N16833081: D102.1 R443.1
N16833084: D103.1 R444.1
N16833087: D104.1 R445.1
N16835391: C407.1 J17.1 R446.1 R447.1
N16848574: C446.1 R482.2 U43.2
N16848598: C445.2 R593.1 U43.1
N16848614: C447.2 R594.1 U43.8
N16848642: R483.1 U43.7
N16848644: C448.2 R483.2 R484.2 U45.3
N16848814: R485.1 U43.6
N16848816: C449.1 R485.2 R486.1 U45.2
N16848832: C449.2 R486.2 R487.1 U45.1
N16848970: U44.6 U44.7
N16848978: C453.2 C454.1 R488.2 R489.2 R492.1 U44.3
N16848994: C454.2 C455.1 R491.1 R493.2 R494.2 U44.2
N16849016: C457.1 R592.1 U44.8
N16851028: U45.6 U45.7
N16851046: C451.1 R595.1 U45.8
N16853569: C458.1 C460.1 R495.2 U48.3
N16853931: C459.1 C460.2 R496.2 R497.1 U48.2
N16853972: C714.2 R569.2 U48.1 U60.2
N16854025: C462.1 C566.1 R597.2 U48.8
N16854569: R500.2 U60.1
N16855013: C466.2 C467.1 R507.2 R508.1 U48.5
N16855828: C465.1 C466.1 R506.2 U48.6
N16855912: C713.2 U48.7 U61.2
N16855916: R503.2 U61.1
N16860426: C471.1 C472.1 R514.1 R515.1 R598.2 U53.1
N16860580: C473.1 C474.1 C475.1 R516.2 U53.8
N16860640: D110.2 D112.1 T1.2 U53.7
N16861373: D111.2 D112.2 D114.2
N16861380: D113.2 D114.1 T1.1 U53.6
N16900365: Q1.1 R537.1 R538.2
N16900541: C505.1 Q1.3 R536.1 U57.7
N16908509: R540.2 R541.2 U57.19
N16935004: R547.2 U57.8
N17022031: C560.1 C561.1 C562.1 R549.1 U58.14
N17025421: C563.1 C564.1 C565.1 R550.1 U59.14
N17096901: C237.2 R133.1 R488.1 R573.2
N17102058: C594.1 R495.1 R506.1 R574.2 R575.1
N17145229: C595.1 R599.2 U28.57
N17182974: C488.1 R49.1 R58.2 R528.1 R529.1
N17183073: C492.1 R532.2 R533.1 R534.1
N17183105: R532.1 U55.2
N17213567: R729.2 R730.2 U28.29
N17215412: R679.1 U28.42
N17215422: R678.1 U28.43
N17215466: C691.2 DAC_5.1 R679.2 R681.2
N17215490: C690.2 DAC_4.1 R678.2 R680.2
N17215663: C687.2 DAC_1.1 R673.2 U28.47
N17215880: C598.1 R607.2 U28.44
N17228521: C698.1 R692.1 R693.1 R694.1 R695.2
N17284506: J5.9 J5.11 R408.1
N17284677: J5.5 R409.1
N17284729: J5.13 R412.2
N17284735: J5.14 R411.2
N17302767: J11.1 R517.2 T2.3
N17302775: J11.2 R517.1 T2.4
N17302818: T1.3 T2.1
N17302820: T1.4 T2.2
N17326807: C711.1 R731.1 Y3.4
N16779431153: R400.1 U28.154

Pads without a net: J4 5 6 7 8 9 10; NOREF#4 1; NOREF#5 1; NOREF#10 1; NOREF#13 1; NOREF#14 1; NOREF#15 1; NOREF#16 1; NOREF#17 1; NOREF#18 1; U28 6 7 9 12 14 17 19 23 24 25 27 28 63 64 65 66 67 69 70 71 73 74 83 84 85 86 87 89 90 92 93 94 95 96 97 98 100 101 102 103 104 105 107 110 111 112 113 115 118 121 128 129 130 131 134 135 136 141 142 145 146 148 149 150 151 155 156 157 161 163 165 167 170 171 172; U57 4 5 17 18 20; Y3 1

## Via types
v1: diameter 0.61, hole 0.305, TOP to BOTTOM, 474 vias

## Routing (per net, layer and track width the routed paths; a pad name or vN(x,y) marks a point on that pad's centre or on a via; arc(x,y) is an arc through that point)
AGND: length 244.3
  TOP w0.381: D125.1 v1(21.28,39.5) ; C711.2 19.94,30.61 Y3.2 21.68,30.9 C712.2 22.48,30.86 v1(22.86,31.24) ; D126.1 v1(18.1,39.5) ; v1(56.52,14.61) 56,15.12 C598.2 ; R705.2 v1(15.24,43.31) ; D124.1 v1(24.45,39.5) ; v1(22.84,29.62) 23.07,29.84 C535.2 ; C540.2 v1(22.86,17.78)
  TOP w0.508: C537.2 v1(22.86,27.3) ; C542.1 28.7,11.43 v1(28.57,11.43) 28.09,11.91 28.09,12.42 C541.1 ; R703.1 27.43,37.47 v1(27.43,36.83) ; C544.1 33.66,11.87 v1(34.1,11.42) ; C378.2 v1(27.3,10.16) ; C708.2 50.8,14.09 C707.2 51.08,15.75 52.88,17.55 52.88,19.13 v1(52.07,19.94) 51.18,19.05 C521.2 ; C709.2 46.48,14.22 C710.2 45.48,15.75 v1(45.09,16.14) ; U58.7 v1(60.96,27.94) ; C554.1 C555.1 51.82,27.94 v1(51.94,27.81) ; R611.1 48.9,30.48 48.64,30.73 v1(48.26,30.73) ; C524.1 v1(40.01,40.64) ; R58.1 C488.2 ; C488.2 R528.2 ; C488.2 53.98,14.47 54.48,14.98 v1(54.71,14.98) ; v1(6.04,35.97) Q1.2 6.04,34.32 6.5,33.86 7.3,33.86 8.89,32.26 R538.1 ; R425.1 R417.1 R421.1 56.52,35.56 v1(57.15,36.2) ; R425.1 R610.1 R420.1 C494.2 ; R425.1 57.4,33.02 v1(57.66,32.77) ; C471.2 v1(79.38,14.61) ; v1(15.24,36.2) 14.93,36.51 D95.1 ; v1(52.07,21.21) 51.69,21.59 C558.1 C559.1 ; C447.1 75.56,22.73 v1(75.18,22.73) ; v1(71.12,22.1) 69.98,20.95 C564.2 ; v1(22.86,22.86) 22.86,23.01 23.35,23.5 C538.2 ; R418.1 C522.1 45.59,40.13 v1(45.09,40.64) ; C530.1 v1(29.21,40.64) ; C525.1 v1(38.73,40.64) ; C563.2 70.05,23.5 70.69,24.13 v1(71.12,24.13) ; D89.1 52.39,7.05 v1(53.34,6.1) ; C520.2 R424.1 v1(48.26,36.83) ; C535.2 C534.2 C533.2 C532.2 ; R445.2 51.82,43.69 52.32,44.2 v1(52.32,44.45) ; C549.1 v1(45.09,11.43) ; R423.1 42.8,40.39 v1(42.55,40.64) ; C545.1 34.92,11.68 v1(35.18,11.43) ; v1(6.24,27.44) 6.23,27.46 C505.2 ; C546.1 v1(36.83,11.43) ; v1(39.62,11.43) 39.5,11.56 C548.1 C547.1 ; C493.2 56.52,20.7 56,20.19 C492.2 56,19.68 ; C526.1 v1(36.2,40.64) ; v1(71.12,23.11) 70.87,23.11 69.98,22.23 C565.2 ; C536.2 v1(22.86,28.57) ; C529.1 v1(30.48,40.64) ; v1(48.51,44.45) 48.51,44.2 48.01,43.69 R444.2 ; C551.1 v1(42.55,11.43) ; 56,19.68 R533.2 ; 56,19.68 56.13,19.81 57.28,19.81 v1(57.4,19.68) ; U59.7 60.73,17.14 v1(61.46,16.42) ; v1(57.78,6.35) 57.15,6.99 C452.2 ; C553.1 51.03,33.12 51.97,33.12 v1(52.07,33.02) ; v1(44.7,44.45) 44.7,44.2 44.2,43.69 R443.2 ; C552.2 C557.1 v1(51.98,24.13) ; v1(50.16,1.4) 50.04,1.4 49.15,2.28 C592.2 ; v1(59.05,6.35) 58.74,6.66 D128.1 ; C697.2 v1(14.61,35.44) ; C472.2 v1(79.38,13.34) ; v1(70.48,34.29) C562.2 C560.2 ; v1(57.53,24.77) 56.9,25.4 U55.3 ; C561.2 v1(70.47,31.75) ; v1(40.64,6.1) 40.96,6.42 D127.1 ; C523.1 44.32,40.13 v1(43.81,40.64) ; C556.1 v1(51.94,26.67) ; C699.2 36.83,7.24 36.2,6.6 v1(36.2,6.35) ; R422.1 v1(38.99,45.21) ; C543.1 32.38,11.93 32.89,11.42 v1(33,11.42) ; C539.2 v1(22.86,20.32) ; v1(45.09,6.35) 45.67,6.93 C593.2 ; R419.1 v1(41.27,40.64) ; R410.1 v1(28.57,10.16) ; R702.2 v1(6.23,37.34) ; C527.1 v1(34.92,40.64) ; R588.2 v1(8.38,37.34) ; C531.2 v1(22.86,34.92) ; C528.1 v1(33.66,40.64) ; C550.1 v1(43.81,11.43)
  TOP w0.635: R711.2 v1(48.77,50.29) ; R717.2 v1(34.16,45.21) ; R723.2 v1(61.09,45.21)
  BOTTOM w0.254: v1(48.26,21.21) 48.68,20.79 U28.33 ; v1(43.81,11.43) 44.71,12.33 U28.52 ; v1(45.09,11.43) 45.22,11.56 U28.51 ; U28.122 23.4,31.79 v1(22.86,31.24) ; v1(45.09,16.14) 45.71,15.51 U28.50 ; U28.32 51.99,21.28 v1(52.07,21.21) 51.15,20.28 U28.34
  BOTTOM w0.381: C519.2 v1(21.08,29.72) ; v1(75.18,22.73) 75.69,22.23 U43.5 ; v1(57.15,36.2) 56.52,35.56 R421.1 ; U57.9 9.88,27.97 v1(10.41,27.44) ; D90.1 42.86,7.71 43.13,7.98 43.97,7.98 C595.2 44.33,6.74 44.72,6.35 v1(45.09,6.35) ; U57.6 7.93,27.96 v1(7.42,27.45) ; D115.1 54.29,6.94 53.44,6.1 v1(53.34,6.1)
  BOTTOM w0.508: v1(67.94,26.42) v1(67.94,29.21) 68.07,29.09 C396.2 ; v1(74.93,24.13) 74.3,23.5 R484.1 C448.1 ; U32.3 v1(65.41,26.42) ; C705.2 61.42,16.39 v1(61.46,16.42) ; v1(54.71,14.98) 53.98,14.25 C488.2 ; C464.2 72.27,30.74 v1(73.11,29.9) ; R446.2 v1(76.83,1.27) ; D85.1 57.22,25.08 v1(57.53,24.77) ; v1(56.52,14.61) 56,14.09 R528.2 ; R673.1 C687.1 49.53,6.48 v1(49.15,6.1) ; v1(55.82,6.35) 55.88,6.41 C489.2 ; v1(66.04,10.79) 65.53,11.31 R681.1 C691.1 ; D86.1 35.24,6.77 35.66,6.35 v1(36.2,6.35) 36.58,6.73 C597.2 ; v1(61.34,21.85) C704.2 ; C703.2 v1(61.34,22.74) ; U61.3 v1(75.03,28.57) ; 76.89,33.66 v1(74.93,33.66) ; U32.2 v1(66.67,26.42) ; U53.4 v1(79.38,19.05) ; C706.2 v1(61.65,14.61) ; U45.5 64.14,22.99 65.66,21.46 v1(66.67,21.46) 67.06,21.08 69.6,21.08 C451.2 ; C596.2 37.98,6.86 v1(37.47,6.35) ; C463.2 74.81,34.8 v1(74.93,34.92) ; C405.2 v1(78.11,1.27) ; v1(64.14,26.42) U32.4 ; v1(53.34,31.75) 53.98,31.11 C408.2 R704.1 ; C407.2 v1(75.56,1.27) ; D92.1 57.09,20 v1(57.4,19.68) ; v1(64.14,16.26) U45.4
  BOTTOM w0.635: v1(16.89,40.76) 16.51,40.76 R692.2 C698.2 R695.1
  vias: v1(2.54,11.43) v1(2.54,10.16) v1(2.54,8.89) v1(3.81,11.43) v1(3.81,10.16) v1(3.81,8.89) v1(4.45,27.3) v1(4.45,26.04) v1(4.45,24.77) v1(5.71,26.04) v1(12.06,27.3) v1(12.06,26.04) v1(12.06,24.77) v1(12.45,5.46) v1(12.45,4.19) v1(13.72,5.46) v1(13.72,4.19) v1(14.61,33.02) v1(14.61,31.11) v1(14.61,29.21) v1(14.61,14.61) v1(14.61,12.06) v1(14.61,9.53) v1(14.61,6.99) v1(14.99,5.46) v1(14.99,4.19) v1(15.24,27.3) v1(16.51,26.67) v1(17.78,13.97) v1(33.15,30.48) v1(33.15,29.21) v1(33.15,27.94) v1(33.15,26.67) v1(33.15,25.4) v1(33.15,24.13) v1(33.15,22.86) v1(34.29,30.48) v1(34.29,29.21) v1(34.29,27.94) v1(34.29,26.67) v1(34.29,25.4) v1(34.29,24.13) v1(34.29,22.86) v1(35.56,30.48) v1(35.56,29.21) v1(35.56,27.94) v1(35.56,26.67) v1(35.56,25.4) v1(35.56,24.13) v1(35.56,22.86) v1(36.83,30.48) v1(36.83,29.21) v1(36.83,27.94) v1(36.83,26.67) v1(36.83,25.4) v1(36.83,24.13) v1(36.83,22.86) v1(38.1,30.48) v1(38.1,29.21) v1(38.1,27.94) v1(38.1,26.67) v1(38.1,25.4) v1(38.1,24.13) v1(38.1,22.86) v1(39.37,30.48) v1(39.37,29.21) v1(39.37,27.94) v1(39.37,26.67) v1(39.37,25.4) v1(39.37,24.13) v1(39.37,22.86) v1(40.64,30.48) v1(40.64,29.21) v1(40.64,27.94) v1(40.64,26.67) v1(40.64,25.4) v1(40.64,24.13) v1(40.64,22.86) v1(41.78,30.48) v1(41.78,29.21) v1(41.78,27.94) v1(41.78,26.67) v1(41.78,25.4) v1(41.78,24.13) v1(41.78,22.86) v1(46.99,1.27) v1(51.44,1.4) v1(52.7,1.4) v1(59.69,1.4) v1(60.96,1.4) v1(66.04,1.27) v1(67.31,1.27) v1(68.58,1.27) v1(69.85,1.27)
SGND: length 36.1
  TOP w0.381: C453.1 v1(98.93,27.3) ; C467.2 v1(98.93,29.84) ; R508.2 v1(98.93,28.57) ; R489.1 v1(98.93,26.04)
  TOP w0.508: C465.2 93.17,29.84 92.45,30.56 v1(92.45,30.77) ; v1(92.59,39.12) R497.2 C459.2 ; v1(88.9,32) 88.9,32.26 89.41,32.77 89.66,32.77 C714.1 C713.1 ; v1(92.71,22.86) 92.97,23.12 R494.1 ; v1(88.9,25.4) 89.41,25.91 R133.2 C237.1 ; C458.2 v1(98.42,36.83)
  BOTTOM w0.381: v1(96.9,22.73) 92.84,22.73 v1(92.71,22.86) ; v1(97.03,34.29) 97.16,34.42 U48.4 ; 97.79,25.4 U44.4 ; v1(92.58,27.94) 92.58,27.53 92.35,27.3 C445.1
  BOTTOM w0.508: C446.2 91.87,23.5 92.51,22.86 v1(92.71,22.86) ; C594.2 95.89,41.02 ; U43.4 v1(88.9,22.23) C457.2 ; 87.29,23.5 v1(88.9,23.5) ; v1(98.3,22.65) 97.79,22.14 U44.5 ; R575.2 97.16,41.02 ; v1(92.45,30.77) 91.6,31.62 C566.2 C462.2
VDD: length 32.9
  TOP w0.508: C554.2 49.02,28.83 v1(48.26,28.83) ; v1(48.26,26.67) C556.2 ; 28.57,36.96 29.21,37.59 C530.2 ; v1(40.64,15.24) 40.64,15.24 C548.2 ; C535.1 v1(26.67,29.84) ; C525.2 v1(38.73,36.83) ; C522.2 45.59,37.08 v1(45.34,36.83) ; v1(26.67,33.93) 26.39,33.66 C532.1 ; C543.2 v1(32.38,15.24) ; C526.2 v1(36.2,36.83)
  BOTTOM w0.254: U28.126 26.52,33.79 v1(26.67,33.93) ; v1(32.38,15.24) 32.71,14.91 U28.76 ; U28.21 48.38,26.79 v1(48.26,26.67) ; v1(36.2,36.83) 36.71,37.35 U28.153 ; U28.169 44.71,37.45 v1(45.34,36.83) ; v1(26.67,29.84) 26.11,29.28 U28.117 ; v1(38.73,36.83) 39.22,37.31 U28.158 ; U28.16 49.2,29.28 48.74,28.83 v1(48.26,28.83) ; v1(28.45,36.83) 28.71,37.1 U28.137 ; v1(40.64,15.24) 40.22,14.82 U28.61
  vias: v1(8.13,5.46) v1(8.13,4.19) v1(9.4,5.46) v1(9.4,4.19) v1(10.67,5.46) v1(10.67,4.19)
/TRST_P: length 13.8
  TOP w0.152: v1(28.57,6.35) R410.2 C378.1 27.3,6.35 26.67,5.71 J5.2
  BOTTOM w0.152: v1(28.57,6.35) 30.54,8.31 30.54,10.47 31.22,11.14 U28.79
/WP_PFC: length 32.1
  ART03 w0.127: v1(47.88,40.68) 64.1,40.68 66.04,38.73 67.31,38.73 v1(67.94,39.37)
  BOTTOM w0.152: v1(47.88,40.68) 47.88,40.04 47.71,39.88 U28.175 ; v1(67.94,39.37) 68.45,38.86 68.45,38.27 69,37.72 69.09,37.72 69.34,37.47 69.34,35.69 69.09,35.44 R439.1 68.58,34.7 68.35,34.47 67.06,34.47 66.67,34.09 U32.7
_AD_DCINPUT: length 13.9
  TOP w0.152: R529.2 48.9,10.41 v1(47.88,11.43)
  BOTTOM w0.152: C489.1 55.88,9.75 55.43,10.2 53.68,10.2 53.34,9.86 53.34,9.53 ; U28.46 47.71,11.59 v1(47.88,11.43) 49.15,10.16 52.7,10.16 53.34,9.53 ; D115.3 53.34,9.53
_AD_DCINPUT_OV: length 13.8
  TOP w0.152: R693.2 C699.1 36.83,9.65 v1(38.61,11.43)
  BOTTOM w0.152: D86.3 34.29,10.41 34.67,10.79 37.29,10.79 37.92,11.43 v1(38.61,11.43) 39.24,12.06 40.39,12.06 40.71,12.39 U28.60
_AD_DCTEMP: length 2.7
  BOTTOM w0.152: C408.1 56.01,31.11 R447.2 R729.1
_OUTPUT_OC: length 53.3
  TOP w0.152: v1(15.24,41.4) 15.88,40.77 D95.3 15.88,39.64 15.59,39.35 14.6,39.35 14.23,38.99 14.23,37.31 13.87,36.95 C697.1 R689.1
  ART03 w0.127: v1(52.1,37.88) 43.81,37.88 41.91,39.79 41.91,40.89 41.4,41.4 41.02,41.4 39.98,42.45 37.37,42.45 35.16,44.66 18.24,44.66 15.24,41.66 v1(15.24,41.4)
  BOTTOM w0.152: v1(52.1,37.88) 51.43,37.21 51.43,36.7 51.02,36.28 U28.2
A_ADC: length 11
  TOP w0.152: R602.2 40.01,7.5 40.64,8.13 40.64,8.64 v1(40.89,8.89)
  BOTTOM w0.152: U28.58 41.71,10.29 41.91,10.09 D90.3 41.91,8.64 41.78,8.51 41.27,8.51 v1(40.89,8.89) R606.1 C596.1
A_ADC1: length 8.6
  BOTTOM w0.152: U28.59 41.22,12.01 40.01,10.79 38.13,10.79 37.64,10.3 37.64,9.23 R606.2 36.58,8.89 C597.1
AD_AIR_TEMP: length 7.8
  TOP w0.152: C493.1 R534.2 55.24,25.34 v1(55.06,25.53)
  BOTTOM w0.152: R730.1 56,26.14 55.39,25.53 v1(55.06,25.53) 55.06,24.28 54.91,24.13 D85.3
AD_DCVOLT1: length 11.5
  TOP w0.152: v1(52.37,11.43) 52.71,11.43 53.34,10.8 D89.3 53.34,9.55 53.62,9.27 54.17,9.27 54.55,9.65 R487.2 C452.1
  BOTTOM w0.152: U28.45 50.44,13.36 v1(52.37,11.43)
B_ADC: length 9.6
  TOP w0.152: D127.3 42.8,9.26 v1(43.05,9.01) 43.34,8.73 R583.2 C593.1
  BOTTOM w0.152: R599.1 43.18,8.89 v1(43.05,9.01) 43.18,9.14 43.18,11.94 42.71,12.4 U28.56
C_ADC: length 16.1
  BOTTOM w0.152: R706.1 58.93,22.61 C704.1 R707.2 58.8,19.68 57.78,20.7 55.5,20.7 55.25,20.45 55.25,19.18 55.12,19.05 D92.3 53.03,19.05 52.87,19.2 52.87,21.3 52.38,21.79 U28.31
CAN5V_GND: length 48
  TOP w0.381: v1(96.76,16.19) 96.64,16.3 96.1,16.3 95.29,15.49 D111.1 95.29,14.69 95.63,14.35 96.66,14.35 v1(96.79,14.48)
  TOP w0.508: 91.44,12.51 v1(91.42,12.48) 90.77,13.13 89.17,13.13 88.88,13.42 D110.1 ; C475.2 v1(87.63,9.53) ; C474.2 v1(88.9,9.53) ; 88.88,19.03 v1(88.9,19.05) ; C473.2 v1(86.36,9.53)
  ART03 w0.508: 86.23,18.92 86.23,42.43 J4.11
  BOTTOM w0.508: U53.5 v1(88.9,19.05)
CAN_5V: length 51.4
  TOP w0.508: R516.1 90.43,10.41 v1(91.44,10.41)
  ART03 w0.508: J4.12 95.5,51.19 95.5,47.59 87.02,39.11 87.02,21.44 v1(87.5,20.95)
  BOTTOM w0.508: v1(91.44,10.41) 92.2,11.18 92.2,18.16 90.3,20.07 88.39,20.07 v1(87.5,20.95)
CANRX: length 67.3
  ART03 w0.127: v1(69.85,12.7) 69.85,12.33 66.67,9.16 55.99,9.16 52.28,12.87 42.26,12.87 41.25,13.88 41.25,16.03 39.69,17.59 30.74,17.59 24.2,24.13 v1(22.86,24.13)
  BOTTOM w0.152: v1(69.85,12.7) 71.12,13.97 U53.2 ; U28.108 23.52,24.79 v1(22.86,24.13) R514.2
CANTX: length 98.2
  ART03 w0.127: v1(25.4,37.59) 25.4,36.92 28.07,34.25 28.07,26.92 26.8,25.65 23.11,25.65 v1(22.86,25.4) 23.58,24.68 24.29,24.68 30.86,18.11 39.93,18.11 41.73,16.3 41.73,14.09 42.61,13.21 52.63,13.21 56.34,9.5 66.38,9.5 69.19,12.3 69.19,16.79 69.55,17.14 70.48,17.14 v1(71.12,16.51)
  BOTTOM w0.152: R515.2 v1(22.86,25.4) 22.98,25.28 U28.109 ; v1(25.4,37.59) 26.16,38.35 26.16,39.62 27.94,41.4 29.32,41.4 29.84,40.88 29.84,40.01 30.22,39.63 U28.140 ; v1(71.12,16.51) U53.3
CS_A: length 76.6
  TOP w0.152: R602.1 40.01,9.01 40.24,9.24 40.24,10.26 39.78,10.71 38.97,10.71 v1(38.28,10.02)
  TOP w0.635: J2.18 14.68,50.17 12.43,47.93 8.85,47.93 7.75,46.83 R603.2 R604.2 R605.2 7.75,39.62 8.02,39.35 v1(8.87,39.35)
  ART03 w0.127: v1(38.28,10.02) 36.77,8.51 25.39,8.51 21.92,11.98 18,11.98 13.47,16.52 13.47,33.51 12.83,34.15 12.83,38 11.97,38.86 9.36,38.86 v1(8.87,39.35)
CS_B: length 83.7
  TOP w0.152: R583.1 46.7,8.73 v1(46.87,8.89)
  TOP w0.635: J2.15 19.04,51.45 19.04,49.06 17.54,47.56 14.67,47.56 R580.2 R581.2 R582.2 12.83,40.15 12.05,39.37 v1(11.43,39.37)
  ART03 w0.127: v1(11.43,39.37) 12.06,39.37 13.34,38.1 13.34,34.45 13.75,34.04 13.75,16.88 17.93,12.7 21.96,12.7 25.65,9.02 36.32,9.02 37.97,10.67 37.97,11.68 38.35,12.06 41.06,12.06 42.58,10.54 45.16,10.54 46.69,9.02 46.74,9.02 v1(46.87,8.89)
CS_C: length 99.4
  TOP w0.635: v1(15.24,42.42) 16.51,42.42 R710.2 R709.2 R708.2 23.31,43.05 23.69,43.43 23.69,49.35 J2.12
  ART03 w0.127: v1(61.59,20.32) 60.46,21.46 60.46,24.64 60.9,25.07 60.9,26.99 61.47,27.56 61.47,29.72 69.72,37.97 69.72,39.75 66.31,43.17 38.19,43.17 35.62,45.74 18.56,45.74 v1(15.24,42.42)
  BOTTOM w0.152: v1(61.59,20.32) 60.96,19.68 R707.1
CS_RTN_A: length 17.1
  TOP w0.635: R702.1 4.95,38.99 R605.1 R604.1 R603.1 4.95,46.74 7.05,48.85 11.37,48.85 J2.20
CS_RTN_B: length 17
  TOP w0.635: R588.1 10.03,38.99 R582.1 R581.1 R580.1 10.03,46.62 10.51,47.09 12.99,47.09 14.61,48.7 16.31,48.7 J2.16
CS_RTN_C: length 12.1
  TOP w0.635: J2.14 22.23,48.27 R708.1 R709.1 R710.1 17.14,45.84 R705.1
DC-OV: length 10.7
  ART03 w0.635: v1(11.56,41.91) 10.16,43.31 J2.22
  BOTTOM w0.635: R694.2 10.42,40.77 v1(11.56,41.91)
DC_FB: length 4.7
  BOTTOM w0.152: J2.24 5.58,52.21 R49.2
DCOVP: length 35.8
  ART03 w0.127: v1(47.88,41.78) 48.65,42.56 66.03,42.56 v1(69.22,39.37)
  BOTTOM w0.152: U28.176 48.22,39.74 48.49,40.02 48.49,41.17 v1(47.88,41.78) ; v1(69.22,39.37) 70.08,39.37 72.39,37.06 R502.2 C463.1 73.78,36.2 U60.4
DCPWM1A_1H: length 49.4
  TOP w0.152: U58.6 60.71,29.21 62.23,30.73 v1(62.23,31.75)
  BOTTOM w0.152: J2.3 34.3,51.44 51.48,51.44 60.4,42.51 60.4,31.48 60.86,31.02 61.5,31.02 v1(62.23,31.75)
DCPWM1A_1HH: length 37.9
  TOP w0.152: v1(42.04,41.78) 42.04,38.23 41.79,37.98 R419.2 ; U58.5 60.83,30.48 61.59,31.24 61.59,32.38 v1(60.96,33.02)
  ART03 w0.127: v1(60.96,33.02) 60.33,33.66 60.33,35.05 56.13,39.24 45.59,39.24 44.45,40.39 44.45,41.51 44.44,41.52 44.45,41.53 44.45,41.78 43.69,42.55 42.8,42.55 v1(42.04,41.78)
  BOTTOM w0.152: v1(42.04,41.78) 41.6,41.34 41.08,41.34 40.64,40.9 40.64,40.23 41.22,39.65 U28.162
DCPWM1A_1L: length 42.5
  TOP w0.152: U58.4 v1(60.96,31.75)
  BOTTOM w0.152: v1(60.96,31.75) 61.58,32.37 61.58,42.1 50.97,52.71 J2.1
DCPWM1A_1LL: length 34.1
  TOP w0.152: U58.3 60.07,33.02 60.96,33.91 v1(60.96,34.29) ; v1(45.72,41.78) 46.35,41.15 47.12,41.15 47.37,40.89 47.37,40.3 47.49,40.18 47.5,40.18 47.68,40 47.68,38.15 47.5,37.98 R418.2
  ART03 w0.127: v1(45.72,41.78) 45.72,40.77 46.86,39.62 56.39,39.62 60.96,35.05 v1(60.96,34.29)
  BOTTOM w0.152: v1(45.72,41.78) 44.45,41.78 43.94,42.29 43.31,42.29 41.99,40.97 41.99,39.85 42.22,39.62 U28.164
DCPWM2A_2H: length 51.9
  TOP w0.152: U58.12 v1(63.25,33.02)
  BOTTOM w0.152: v1(63.25,33.02) 62.87,33.4 62.87,42.57 51.16,54.28 29.5,54.28 J2.7
DCPWM2A_2HH: length 36
  TOP w0.152: v1(62.23,33.02) 62.95,33.74 63.84,33.74 64.4,34.29 U58.13 ; v1(51.94,29.72) 52.45,29.21 R420.2
  ART03 w0.127: v1(62.23,33.02) 62.23,32.64 61.59,32 61.59,31.24 60.45,30.1 60.45,25.53 60.07,25.15 60.07,22.23 58.55,20.7 57.66,20.7 56.77,21.59 56.77,26.29 53.34,29.72 v1(51.94,29.72)
  BOTTOM w0.152: U28.18 51.53,28.28 51.94,28.7 v1(51.94,29.72)
DCPWM2A_2L: length 47.1
  TOP w0.152: v1(62.23,35.43) 61.66,34.86 60.64,34.86 60.07,34.29 U58.2
  BOTTOM w0.152: v1(62.23,35.43) 62.23,42.32 50.67,53.88 31.64,53.88 J2.5
DCPWM2A_2LL: length 14.8
  TOP w0.152: R421.2 54.49,36.7 v1(53.34,37.85) ; U58.1 v1(57.91,35.56)
  ART03 w0.127: v1(53.34,37.85) 56.39,37.85 57.91,36.32 v1(57.91,35.56)
  BOTTOM w0.152: U28.1 50.68,36.79 50.95,37.06 50.95,37.62 51.79,38.46 52.73,38.46 v1(53.34,37.85)
DCPWM3A_3H: length 60.9
  TOP w0.152: U58.8 63.63,27.94 v1(63.25,28.32)
  BOTTOM w0.152: J2.11 24.1,51.47 24.1,49.46 25.24,48.33 53.14,48.33 59.44,42.03 59.44,30.83 60.17,30.1 62.86,30.1 63.25,29.72 v1(63.25,28.32)
DCPWM3A_3HH: length 22.8
  TOP w0.152: U58.9 63.12,29.21 62.23,28.32 v1(62.23,27.94)
  BOTTOM w0.152: v1(62.23,27.94) 62.74,28.45 62.74,29.57 62.59,29.72 60.07,29.72 59.05,30.73 59.05,33.27 57.91,34.42 54.99,34.42 54.49,34.92 R416.2 53.34,35.56 52.06,34.28 50.14,34.28
DCPWM3A_3L: length 56.3
  TOP w0.152: U58.10 v1(63.5,30.48)
  BOTTOM w0.152: J2.9 26.66,51.45 26.66,49.6 27.46,48.8 53.33,48.8 59.87,42.26 59.87,31.35 60.74,30.48 v1(63.5,30.48)
DCPWM3A_3LL: length 22
  TOP w0.152: R417.2 v1(53.21,34.29) ; U58.11 63.5,31.75 62.7,30.95 62.7,29.68 v1(62.23,29.21)
  BOTTOM w0.152: v1(62.23,29.21) 59.9,29.21 58.55,30.56 58.55,33.25 58.14,33.66 53.85,33.66 v1(53.21,34.29) 52.58,33.66 51.44,33.66 51.06,33.28 U28.8
DCSHORT: length 38.3
  ART03 w0.127: v1(53.21,36.83) 55.51,36.83 59.83,32.51 61.21,32.51 61.59,32.89 61.59,33.4 61.91,33.72 64.83,33.72 69.22,38.1 v1(69.22,38.23)
  BOTTOM w0.152: v1(69.22,38.23) 69.85,37.59 69.85,34.05 70.24,33.66 73.28,33.66 73.78,33.15 R505.2 C464.1 U61.4 ; U28.5 51.17,34.79 v1(53.21,36.83)
DCVOLT1: length 8.4
  TOP w0.152: C455.2 R491.2 91.72,23.01 92.05,23.01 92.66,23.62 v1(92.66,24.03)
  BOTTOM w0.152: U44.1 93.98,25.97 93.62,25.61 92.49,25.61 91.64,24.77 R482.1 92.3,24.03 v1(92.66,24.03)
IOUT_ADC: length 76.9
  TOP w0.152: R607.1 56.52,17.27 59.69,14.1 D128.3 v1(59.69,8.26)
  ART03 w0.127: v1(59.69,8.26) 59.91,8.47 67.76,8.47 71.71,12.42 71.71,29.53 73.59,31.41 73.59,48.14 70.3,51.44 60.97,51.44 J3.4
OUTPUT_OC: length 60.7
  TOP w0.152: R689.2 11.43,35.35 12.39,34.39 12.39,34.09 R691.2 14.09,33.78 v1(14.61,34.29)
  ART03 w0.127: v1(14.61,34.29) 13.84,35.05 13.84,43.12 17.97,47.24 38.48,47.24 43.95,52.71 J3.2
P_ADREF3.2V: length 14.1
  TOP w0.508: C549.2 45.09,14.86 v1(44.71,15.23) ; C551.2 42.55,14.94 ; v1(48.26,20.19) 48.39,20.32 C559.2 C558.2
  BOTTOM w0.254: U28.37 49.09,18.79 49.01,18.7 47.72,18.7 v1(47.12,19.3) ; U28.35 48.67,19.79 v1(48.26,20.19) ; U28.53 44.22,14.73 v1(44.71,15.23) ; U28.55 43.22,14.98 v1(42.9,15.29)
  vias: v1(50.16,3.81)
P_SCL: length 32.3
  ART03 w0.127: v1(66.67,39.37) 64.77,41.27 47.24,41.27 v1(46.74,41.78)
  BOTTOM w0.152: U28.174 47.22,40.25 47.32,40.35 47.32,41.2 v1(46.74,41.78) ; v1(66.67,39.37) 67.44,38.61 67.44,35.66 67.21,35.44 R438.1 66.04,35.44 65.41,34.8 U32.6
